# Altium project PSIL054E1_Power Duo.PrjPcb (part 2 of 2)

## Sheet PSIL054E1_FTDI.SchDoc
size 431 x 279 mm; Date: Not shown in title block; ApprovedBy: Not shown in title block; CheckedBy: Not shown in title block; Author: Not shown in title block; CompanyName: Not shown in title block; Engineer: Not shown in title block; Organization: Not shown in title block; Address1: Not shown in title block; Address2: Not shown in title block; Address3: Not shown in title block; Address4: Not shown in title block; DocumentNumber: 1; Revision: Use project parameter SCH_Rev; SheetNumber: 7; SheetTotal: 9; PageSetup: Record=PageOptions¦CenterHorizontal=True¦CenterVertical=True¦PrintScale=1.00¦XCorrection=1.00¦YCorrection=1.00¦PrintKind=0¦BorderSize=5000000¦LeftOffset=0¦BottomOffset=0¦Orientation=2¦PaperLength=1000¦PaperWidth=1000¦Scale=100¦PaperSource=15¦PrintQuality=600¦MediaType=1¦DitherType=10¦PaperKind=Letter¦PrintScaleMode=1
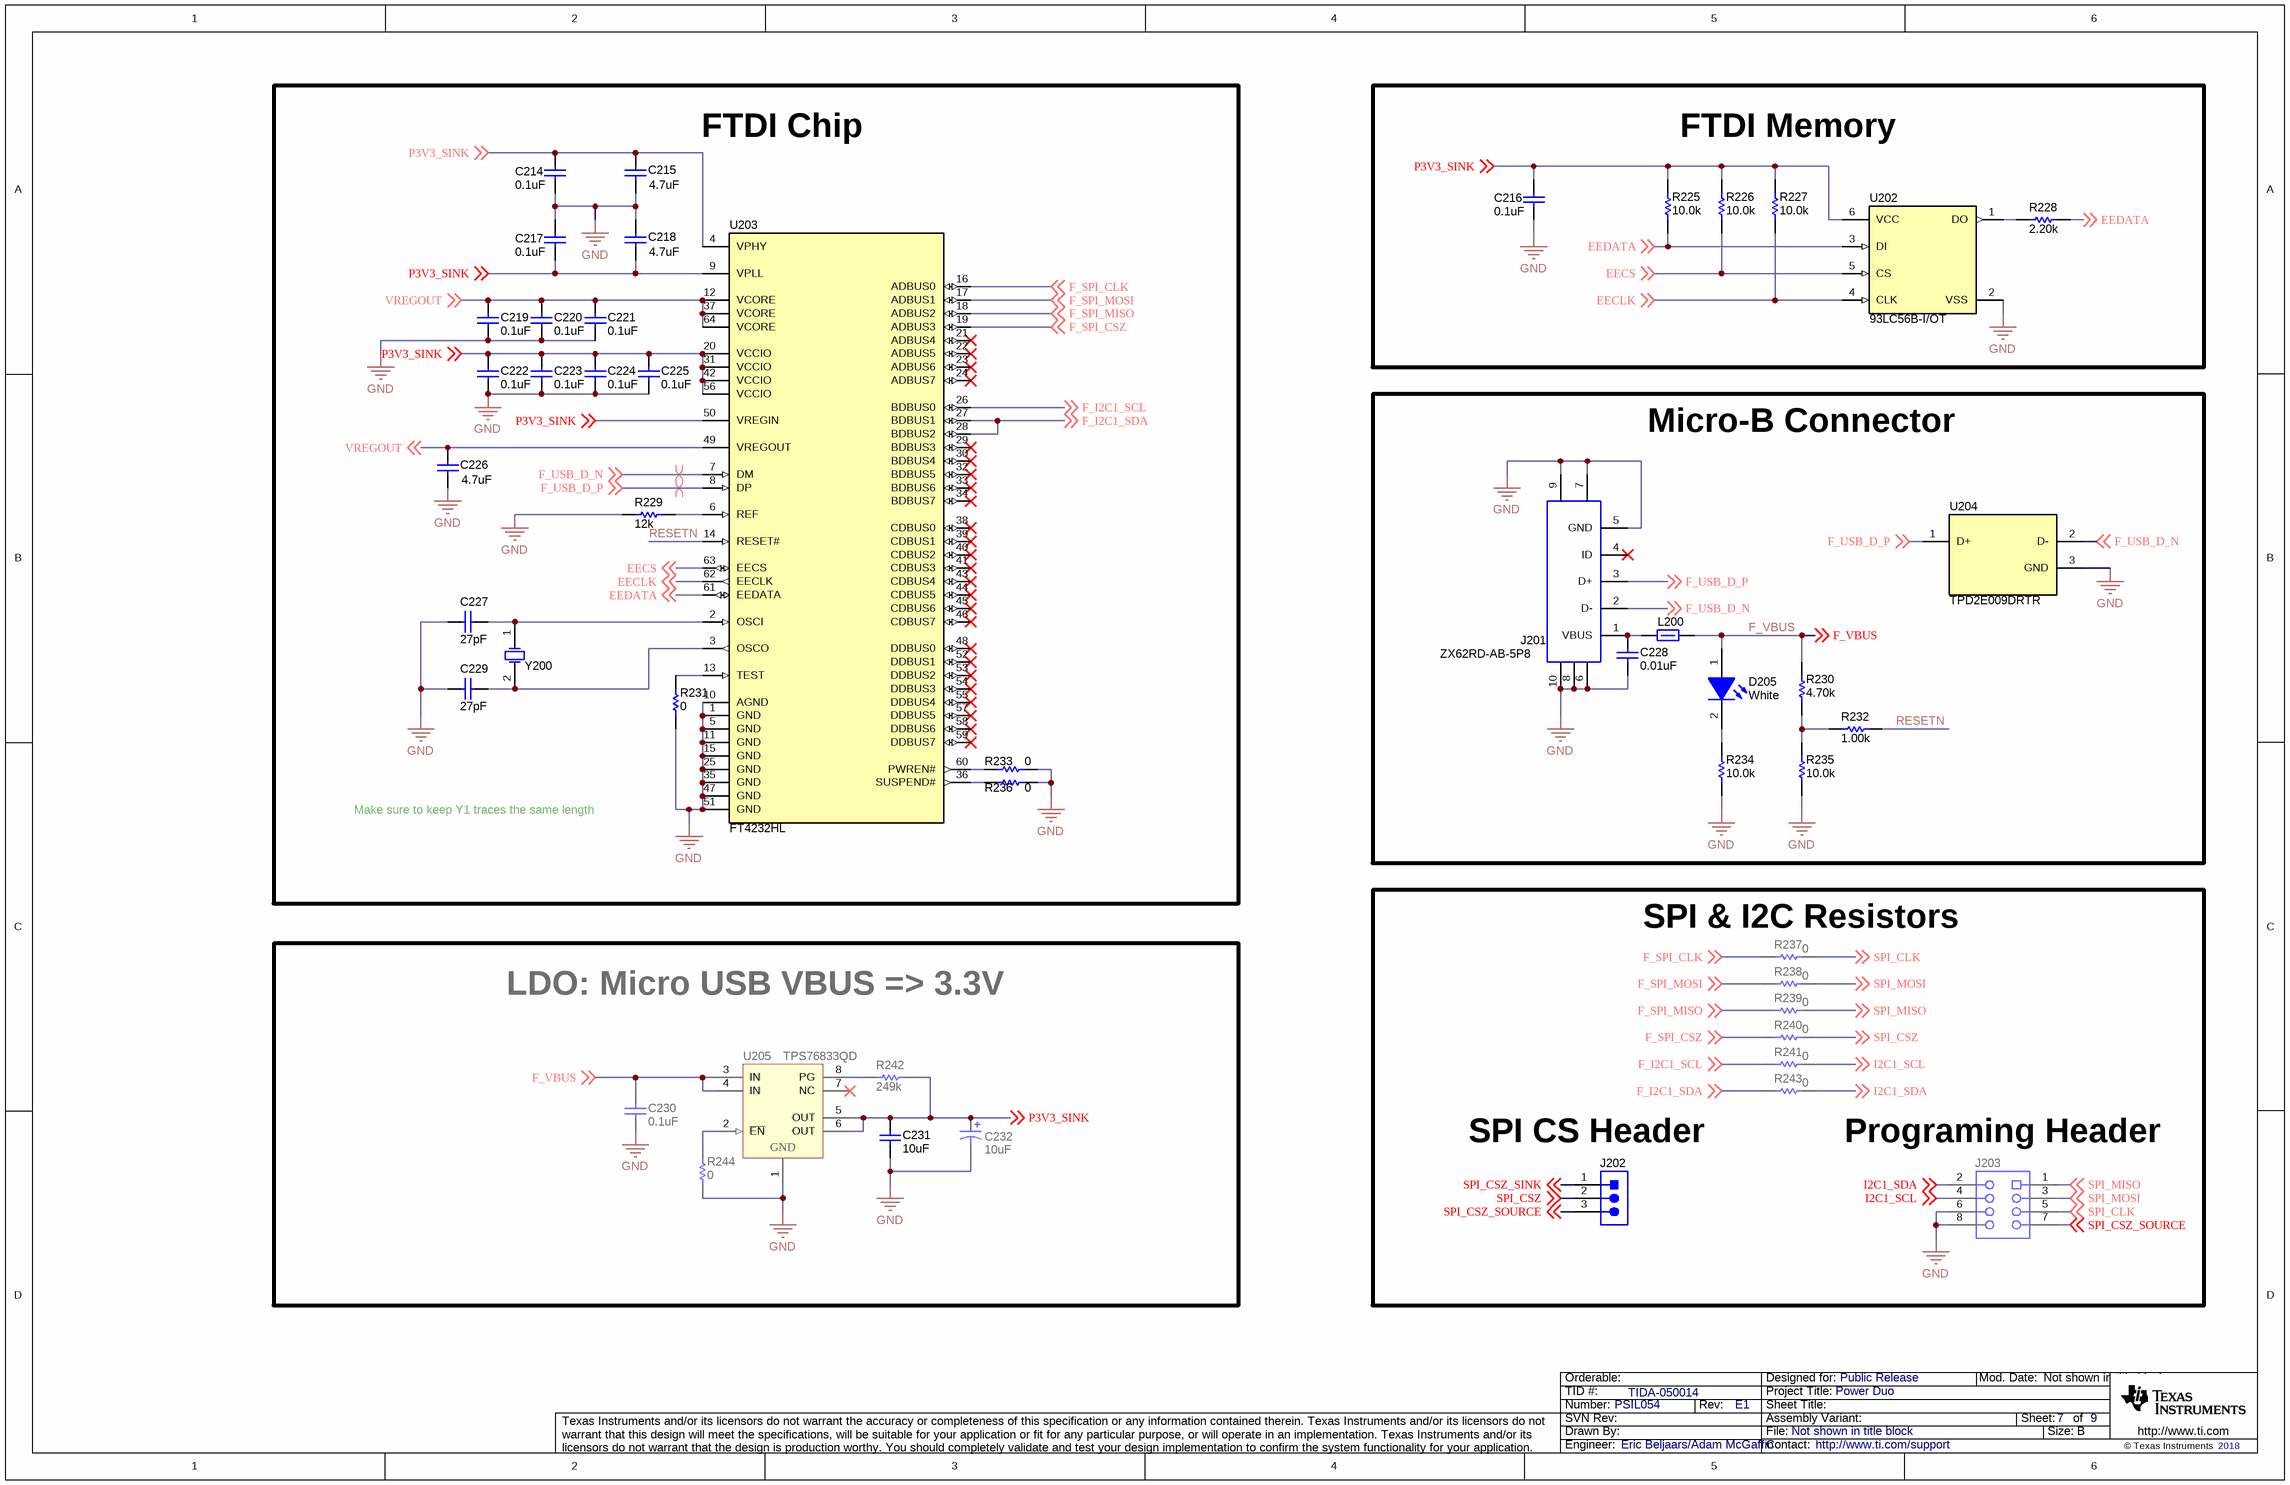
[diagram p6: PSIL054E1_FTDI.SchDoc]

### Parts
C214  value 0.1uF  [0402]  (hidden comment: C1005X7R1H104K050BB)
C215  ValueDisplayed: 4.7uF  [0402]  (hidden comment: C1005X5R1A475M050BC)
C216  value 0.1uF  [0402L]  (hidden comment: C1005X7R1H104K050BB)
C217  value 0.1uF  [0402]  (hidden comment: C1005X7R1H104K050BB)
C218  ValueDisplayed: 4.7uF  [0402]  (hidden comment: C1005X5R1A475M050BC)
C219  value 0.1uF  [0402]  (hidden comment: C1005X7R1H104K050BB)
C220  value 0.1uF  [0402]  (hidden comment: C1005X7R1H104K050BB)
C221  value 0.1uF  [0402]  (hidden comment: C1005X7R1H104K050BB)
C222  value 0.1uF  [0402]  (hidden comment: C1005X7R1H104K050BB)
C223  value 0.1uF  [0402]  (hidden comment: C1005X7R1H104K050BB)
C224  value 0.1uF  [0402]  (hidden comment: C1005X7R1H104K050BB)
C225  value 0.1uF  [0402]  (hidden comment: C1005X7R1H104K050BB)
C226  ValueDisplayed: 4.7uF  [0402]  (hidden comment: C1005X5R1A475M050BC)
C227  ValueDisplayed: 27pF  [0603]  (hidden comment: CL10C270FB8NNNC)
C228  ValueDisplayed: 0.01uF  [0402]  (hidden comment: C0402C103J5RACTU)
C229  ValueDisplayed: 27pF  [0603]  (hidden comment: CL10C270FB8NNNC)
C230  value 0.1uF  [0402]  (hidden comment: C1005X7R1H104K050BB)
C231  ValueDisplayed: 10uF  [0805_HV]  (hidden comment: C2012X5R1V106K085AC)
C232  ValueDisplayed: 10uF  [3528-21]  (hidden comment: 293D106X9010B2TE3)
D205  value White  [LW QH8G_White]  (hidden comment: LW QH8G-Q2S2-3K5L-1)
J201  ZX62RD-AB-5P8  [Hirose_ZX62RD-AB-5P8]
J202  TSW-103-07-G-S  [TSW-103-07-G-S]  (value not drawn)
J203  SSQ-104-03-G-D  [Samtec_SSQ-104-03-x-D]  (value not drawn)
L200  BLM18SG260TN1D  [0603]  (value not drawn)
R225  ValueDisplayed: 10.0k  [0402]  (hidden comment: ERJ-2RKF1002X)
R226  ValueDisplayed: 10.0k  [0402]  (hidden comment: ERJ-2RKF1002X)
R227  ValueDisplayed: 10.0k  [0402]  (hidden comment: ERJ-2RKF1002X)
R228  ValueDisplayed: 2.20k  [0402]  (hidden comment: RC0402FR-072K2L)
R229  value 12k  [0402]  (hidden comment: CRCW040212K0JNED)
R230  ValueDisplayed: 4.70k  [0402]  (hidden comment: ERJ-2RKF4701X)
R231  ValueDisplayed: 0  [0402]  (hidden comment: CRCW04020000Z0ED)
R232  ValueDisplayed: 1.00k  [0402]  (hidden comment: ERJ-2RKF1001X)
R233  ValueDisplayed: 0  [0402]  (hidden comment: CRCW04020000Z0ED)
R234  ValueDisplayed: 10.0k  [0402]  (hidden comment: ERJ-2RKF1002X)
R235  ValueDisplayed: 10.0k  [0402]  (hidden comment: ERJ-2RKF1002X)
R236  ValueDisplayed: 0  [0402]  (hidden comment: CRCW04020000Z0ED)
R237  ValueDisplayed: 0  [0402]  (hidden comment: CRCW04020000Z0ED)
R238  ValueDisplayed: 0  [0402]  (hidden comment: CRCW04020000Z0ED)
R239  ValueDisplayed: 0  [0402]  (hidden comment: CRCW04020000Z0ED)
R240  ValueDisplayed: 0  [0402]  (hidden comment: CRCW04020000Z0ED)
R241  ValueDisplayed: 0  [0402]  (hidden comment: CRCW04020000Z0ED)
R242  ValueDisplayed: 249k  [0603]  (hidden comment: CRCW0603249KFKEA)
R243  ValueDisplayed: 0  [0402]  (hidden comment: CRCW04020000Z0ED)
R244  ValueDisplayed: 0  [0402]  (hidden comment: CRCW04020000Z0ED)
U202  93LC56B-I/OT  [SOT-23-6]
U203  FT4232HL  [LQFP64_N]
U204  TPD2E009DRTR  [DRT0003A]
U205  TPS76833QD  [D0008A_N]
Y200  ECS-120-20-3X-TR  [ECS_CSM-3X]  (value not drawn)

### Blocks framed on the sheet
FTDI Chip: C214 C215 C217-C227 C229 R229 R231 R233 R236 U203 Y200
FTDI Memory: C216 R225-R228 U202
Micro-B Connector: C228 D205 J201 L200 R230 R232 R234 R235 U204
LDO: Micro USB VBUS => 3.3V: C230-C232 R242 R244 U205

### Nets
GND: C214.2 C215.2 C216.2 C217.1 C218.1 C219.2 C220.2 C221.2 C222.2 C223.2 C224.2 C225.2 C226.2 C227.1 C228.2 C229.1 C230.2 C231.2 C232.2(-) J201.5(GND) J201.6 J201.7 J201.8 J201.9 J201.10 J203.6 J203.8 R229.2 R231.2 R233.2 R234.1 R235.1 R236.2 R244.2 U202.2(VSS) U203.1(GND) U203.5(GND) U203.10(AGND) U203.11(GND) U203.15(GND) U203.25(GND) U203.35(GND) U203.47(GND) U203.51(GND) U204.3(GND) U205.1(GND)
EECLK: R227.1 U202.4(CLK) U203.62(EECLK) ; off-sheet EECLK
EECS: R226.1 U202.5(CS) U203.63(EECS) ; off-sheet EECS
EEDATA: R225.1 R228.2 U202.3(DI) U203.61(EEDATA) ; off-sheet EEDATA
F_I2C1_SCL: R241.1 U203.26(BDBUS0) ; off-sheet F_I2C1_SCL
F_I2C1_SDA: R243.1 U203.27(BDBUS1) U203.28(BDBUS2) ; off-sheet F_I2C1_SDA
F_SPI_CLK: R237.1 U203.16(ADBUS0) ; off-sheet F_SPI_CLK
F_SPI_CSZ: R240.1 U203.19(ADBUS3) ; off-sheet F_SPI_CSZ
F_SPI_MISO: R239.1 U203.18(ADBUS2) ; off-sheet F_SPI_MISO
F_SPI_MOSI: R238.1 U203.17(ADBUS1) ; off-sheet F_SPI_MOSI
F_USB_D_N: J201.2(D-) U203.7(DM) U204.2(D-) ; off-sheet F_USB_D_N
F_USB_D_P: J201.3(D+) U203.8(DP) U204.1(D+) ; off-sheet F_USB_D_P
F_VBUS: C230.1 D205.1(A) L200.2 R230.2 U205.3(IN) U205.4(IN) ; off-sheet F_VBUS
I2C1_SCL: J203.4 R241.2 ; off-sheet I2C1_SCL
I2C1_SDA: J203.2 R243.2 ; off-sheet I2C1_SDA
P3V3_SINK: C214.1 C215.1 C216.1 C217.2 C218.2 C222.1 C223.1 C224.1 C225.1 C231.1 C232.1(+) R225.2 R226.2 R227.2 R242.2 U202.6(VCC) U203.4(VPHY) U203.9(VPLL) U203.20(VCCIO) U203.31(VCCIO) U203.42(VCCIO) U203.50(VREGIN) U203.56(VCCIO) U205.5(OUT) U205.6(OUT) ; off-sheet P3V3_SINK
RESETN: R232.2 U203.14(RESET#)
SPI_CLK: J203.5 R237.2 ; off-sheet SPI_CLK
SPI_CSZ: J202.2 R240.2 ; off-sheet SPI_CSZ
SPI_CSZ_SINK: J202.1 ; off-sheet SPI_CSZ_SINK
SPI_CSZ_SOURCE: J202.3 J203.7 ; off-sheet SPI_CSZ_SOURCE
SPI_MISO: J203.1 R239.2 ; off-sheet SPI_MISO
SPI_MOSI: J203.3 R238.2 ; off-sheet SPI_MOSI
VREGOUT: C219.1 C220.1 C221.1 C226.1 U203.12(VCORE) U203.37(VCORE) U203.49(VREGOUT) U203.64(VCORE) ; off-sheet VREGOUT
NetC227_2: C227.2 U203.2(OSCI) Y200.1(OSC1)
NetC228_1: C228.1 J201.1(VBUS) L200.1
NetC229_2: C229.2 U203.3(OSCO) Y200.2(OSC2)
NetD205_2: D205.2(K) R234.2
NetR228_1: R228.1 U202.1(DO)
NetR229_1: R229.1 U203.6(REF)
NetR230_1: R230.1 R232.1 R235.2
NetR231_1: R231.1 U203.13(TEST)
NetR233_1: R233.1 U203.60(PWREN#)
NetR236_1: R236.1 U203.36(SUSPEND#)
NetR242_1: R242.1 U205.8(PG)
NetR244_1: R244.1 U205.2(~{EN})

Not connected (* = marked no-connect by the designer): J201 4(ID)*; U203 21(ADBUS4)* 22(ADBUS5)* 23(ADBUS6)* 24(ADBUS7)* 29(BDBUS3)* 30(BDBUS4)* 32(BDBUS5)* 33(BDBUS6)* 34(BDBUS7)* 38(CDBUS0)* 39(CDBUS1)* 40(CDBUS2)* 41(CDBUS3)* 43(CDBUS4)* 44(CDBUS5)* 45(CDBUS6)* 46(CDBUS7)* 48(DDBUS0)* 52(DDBUS1)* 53(DDBUS2)* 54(DDBUS3)* 55(DDBUS4)* 57(DDBUS5)* 58(DDBUS6)* 59(DDBUS7)*; U205 7(NC)*

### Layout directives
differential pair: F_USB_D_N, F_USB_D_P

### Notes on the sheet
- Make sure to keep Y1 traces the same length
- (near R237) SPI & I2C Resistors
- (near J202) SPI CS Header
- (near J203) Programing Header

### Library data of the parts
C214 C217 C219-C225 C230 = CMP-0006297-1: CAP, CERM, 0.1 uF, 50 V, +/- 10%, X7R, 0402; Manufacturer: TDK; TaMin_C: -55°C; ESR_ohm: 0.039064; Polarized: N; SizeAreaWB_mm2: 3; Value1: 0.039064 ohm; U/M: EA; TaMax_C: 125°C; SizeZ_mm: 0.6; SizeX_mm: 1; SizeY_mm: 0.5; Value2: 50V; CompType: Capacitor; Cap_F: 100nF; IRMS_A: 8.14669dA; AEC Category: Q200
C215 C218 C226 = CMP-0006269-2: CAP, CERM, 4.7 uF, 10 V, +/- 20%, X5R, 0402; Manufacturer: TDK; TaMin_C: -55°C; Polarized: N; SizeAreaWB_mm2: 3; Value1: Unknown; U/M: EA; Value: 4.7uF; TaMax_C: 85°C; SizeZ_mm: 0.6; SizeX_mm: 1; SizeY_mm: 0.5; Value2: 10V; CompType: Capacitor; Cap_F: 4.7µF; AEC Category: Q200
C216 = CMP-0006297-1: CAP, CERM, 0.1 uF, 50 V, +/- 10%, X7R, 0402; Manufacturer: TDK; TaMin_C: -55°C; ESR_ohm: 0.039064; Polarized: N; SizeAreaWB_mm2: 3; Value1: 0.039064 ohm; U/M: EA; TaMax_C: 125°C; SizeZ_mm: 0.6; SizeX_mm: 1; SizeY_mm: 0.5; Cap_Case: 0402; Value2: 50V; CompType: Capacitor; Cap_F: 100nF; IRMS_A: 8.14669dA; AEC Category: Q200
C227 C229 = CMP-0007116-4: CAP, CERM, 27 pF, 50 V, +/- 1%, C0G/NP0, 0603; Manufacturer: Samsung Electro-Mechanics; TaMin_C: -55°C; Polarized: N; SizeAreaWB_mm2: 4.68; Value1: Unknown; U/M: EA; Value: 27pF; TaMax_C: 125°C; SizeZ_mm: 1; SizeX_mm: 1.6; SizeY_mm: 0.8; Value2: 50V; SizeArea_mm2: 1.28; CompType: Capacitor; AEC Category: Q200
C228 = CMP-0006236-2: CAP, CERM, 0.01 uF, 50 V, +/- 5%, X7R, 0402; Manufacturer: Kemet; TaMin_C: -55°C; Polarized: N; SizeAreaWB_mm2: 3; Value1: Unknown; U/M: EA; Value: 0.01uF; TaMax_C: 125°C; SizeZ_mm: 0.6; SizeX_mm: 1; SizeY_mm: 0.5; Value2: 50V; CompType: Capacitor; Cap_F: 10nF; AEC Category: Q200
C231 = CMP-0007842-2: CAP, CERM, 10 uF, 35 V, +/- 10%, X5R, 0805; Manufacturer: TDK; TaMin_C: -55°C; ESR_ohm: 2.818m; Polarized: N; SizeAreaWB_mm2: 6.75; Value1: 0.002818 ohm; U/M: EA; Value: 10uF; TaMax_C: 85°C; SizeZ_mm: 1.45; SizeX_mm: 2; SizeY_mm: 1.25; Cap_Case: 0805; Value2: 35V; SizeArea_mm2: 2.5; CompType: Capacitor; Cap_F: 10µF; IRMS_A: 3.88676A; AEC Category: Q200
C232 = CMP-0011512-2: CAP, TA, 10 uF, 10 V, +/- 10%, 2.5 ohm, SMD; Manufacturer: Vishay-Sprague; TaMin_C: -55°C; ESR_ohm: 2.5; Polarized: Y; SizeAreaWB_mm2: 17.1; Value1: 2.5 ohm; U/M: EA; Value: 10uF; TaMax_C: 125°C; SizeZ_mm: 2.1; SizeX_mm: 3.5; SizeY_mm: 2.8; Cap_Case: B; Value2: 10V; SizeArea_mm2: 9.8; CompType: Capacitor; Cap_F: 10µF; IRMS_A: 1.8dA; AEC Category: Q200
D205 = CMP-0002919-1: LED, White, SMD; Manufacturer: OSRAM; Io_A: 5mA; Vr_V: 5V; Tjmax_C: 95°C; Value1: W; U/M: EA; Angle: 120; Ir_A: 10nA; Vf_V: 2.8V
J201 = CMP-0075126-1: Connector, Receptacle, Micro-USB Type AB, R/A, Bottom Mount SMT; Manufacturer: Hirose Electric Co. Ltd.; Alternate PartNumber: ZX62RD-AB-5P8(30); CNHeader: False; Gender: Female; CompType: USB; Row_Count: 1; Pitch_mm: 0.65; CT: True
J202 = CMP-0075407-2: Header, 100mil, 3x1, Gold, TH; Manufacturer: Samtec; Pitch_mm: 2.54; Cert_VDE: N; Gender: Male; Cert_CSA: Y; Voltage_V: 550V; Green_REACh: Passed; Current_A: 6.3A; Green_Lifecycle: Active; Row_Count: 1
J203 = CMP-0055685-1: Receptacle, 2.54mm, 4x2, Gold, TH; Manufacturer: Samtec; CNHeader: FALSE; Current_A: 6.3A; Gender: Female; Cert_CSA: Y; CompType: Socket Strip; Row_Count: 2; RowSpacing_mm: 2.54; CT: TRUE
L200 = CMP-0003354-2: Ferrite Bead, 26 ohm @ 100 MHz, 6 A, 0603; Manufacturer: MuRata; ZTyp@100MHz_Ohm: 26; SizeAreaWB_mm2: 4.68; DCR_ohm: 7m; Value1: 0.007 ohm; Value: 26 ohm; Imax_A: 6A; SizeZ_mm: 1; SizeX_mm: 1.6; SizeY_mm: 0.8; SizeArea_mm2: 1.28
R225-R227 R234 R235 = CMP-0026658-1: RES, 10.0 k, 1%, 0.1 W, 0402; Manufacturer: Panasonic; Power_W: 100mW; TempCo: 100 ppm/C; Value_Code: 10k0; U/M: EA; Value: 10.0k; EIA_Code: E96; Res_ohm: 10k; SizeX_mm: 1; SizeY_mm: 0.5; SizeZ_mm: 0.6; Value2: 0.1W; VDC_V: 50V; AEC Category: Q200
R228 = CMP-0026729-1: RES, 2.20 k, 1%, 0.063 W, 0402; Manufacturer: Yageo America; Power_W: 63mW; TempCo: 100 ppm/C; Value_Code: 2k20; U/M: EA; Value: 2.20k; Res_ohm: 2.2k; SizeX_mm: 1; SizeY_mm: 0.5; SizeZ_mm: 0.6; Value2: 0.063W; AEC Qualified: N; AEC Category: Q200
R229 = CMP-0026834-2: RES, 12 k, 5%, 0.063 W, 0402; Manufacturer: Vishay-Dale; Power_W: 63mW; TempCo: 200 ppm/C; Value_Code: 12k0; U/M: EA; EIA_Code: E24; SizeX_mm: 1; SizeY_mm: 0.5; SizeZ_mm: 0.6; Value2: 0.063W; CompType: Resistor; VDC_V: 50V; AEC Category: Q200
R230 = CMP-0026700-1: RES, 4.70 k, 1%, 0.1 W, 0402; Manufacturer: Panasonic; Power_W: 100mW; TempCo: 100 ppm/C; Value_Code: 4k70; U/M: EA; Value: 4.70k; Res_ohm: 4.7k; SizeX_mm: 1; SizeY_mm: 0.5; SizeZ_mm: 0.6; Value2: 0.1W; VDC_V: 50V; AEC Category: Q200
R231 R233 R236-R241 R243 R244 = CMP-0026822-3: RES, 0, 5%, 0.063 W, AEC-Q200 Grade 0, 0402; Manufacturer: Vishay-Dale; Power_W: 63mW; TempCo: 200 ppm/C; Value_Code: 0000; Value: 0; EIA_Code: E24; SizeX_mm: 1; SizeY_mm: 0.5; SizeZ_mm: 0.6; Value2: 0.063W; AEC Qualified: Y; VDC_V: 50V; AEC Category: Q200
R232 = CMP-0026657-1: RES, 1.00 k, 1%, 0.1 W, 0402; Manufacturer: Panasonic; Power_W: 100mW; TempCo: 100 ppm/C; Value_Code: 1k00; U/M: EA; Value: 1.00k; EIA_Code: E96; Res_ohm: 1k; SizeX_mm: 1; SizeY_mm: 0.5; SizeZ_mm: 0.6; Value2: 0.1W; VDC_V: 50V; AEC Category: Q200
R242 = CMP-0022234-4: RES, 249 k, 1%, 0.1 W, AEC-Q200 Grade 0, 0603; Manufacturer: Vishay-Dale; Power_W: 100mW; TempCo: 100 ppm/C; Value: 249k; EIA_Code: E96; SizeX_mm: 1.6; SizeY_mm: 0.8; SizeZ_mm: 1; Value2: 0.1W; SizeArea_mm2: 1.28; AEC Qualified: Y; VDC_V: 75V; AEC Category: Q200; AEC Grade: 0
U202 = CMP-0005250-2: 2K Microwire Compatible Serial EEPROM, SOT-23-6; Manufacturer: Microchip; SizeZ_mm: 1.15; SizeX_mm: 2.9; SizeY_mm: 2.8; SizeArea_mm2: 8.12; SizeAreaWB_mm2: 14.82
U203 = CMP-0004747-1: Quad High Speed USB to Multipurpose UART/MPSSE IC; Manufacturer: FTDI
U204 = CMP-0043102-2: ESD Protection Array for High-Speed Data Interfaces, 2 Channels, -40 to +85 degC, 3-pin SOT (DRT), Green (RoHS & no Sb/Br); Manufacturer: Texas Instruments; IO Leakage Current(nA): 10; IO Capacitance(Typ)(pF): 0.7; Serial ATA / eSATA: TRUE; SubFamily: ESD Solution; Breakdown Voltage(Min)(V): 9; Differential Capacitance(pF): 0.01; IEC 61000-4-2 Air-Gap(+/- kV): 8
U205 = CMP-0036484-1: Single Output Fast Transient Response LDO, 1 A, Fixed 3.3 V Output, 2.7 to 10 V Input, with Low IQ, 8-pin SOIC (D), -40 to 125 degC, Green (RoHS & no Sb/Br); Manufacturer: Texas Instruments; Iout(Max)(A): 1; SubFamily: Single Channel LDO; Accuracy(%): 2; Vout Adj(Max)(V): 3.3; Power Good: TRUE; Vin(Min)(V): 2.7; Vdo(Typ)(mV): 350; Iq(Typ)(mA): 0.08; Vin(Max)(V): 10
Y200 = CMP-0004584-3: CRYSTAL, 12 MHz, 20pF, SMD; Manufacturer: ECS Inc.; TaMin_C: -10°C; Frequency Stability: +/-50ppm; Frequency_Fixed: 12MHz; TaMax_C: 70°C

## Sheet PSIL054E1_Sink Buttons LEDs.SchDoc
size 431 x 279 mm; Date: Not shown in title block; ApprovedBy: Not shown in title block; CheckedBy: Not shown in title block; Author: Not shown in title block; CompanyName: Not shown in title block; Engineer: Not shown in title block; Organization: Not shown in title block; Address1: Not shown in title block; Address2: Not shown in title block; Address3: Not shown in title block; Address4: Not shown in title block; DocumentNumber: 1; Revision: Use project parameter SCH_Rev; SheetNumber: 8; SheetTotal: 9; PageSetup: Record=PageOptions¦CenterHorizontal=True¦CenterVertical=True¦PrintScale=1.00¦XCorrection=1.00¦YCorrection=1.00¦PrintKind=0¦BorderSize=5000000¦LeftOffset=0¦BottomOffset=0¦Orientation=2¦PaperLength=1000¦PaperWidth=1000¦Scale=100¦PaperSource=15¦PrintQuality=600¦MediaType=1¦DitherType=10¦PaperKind=Letter¦PrintScaleMode=1
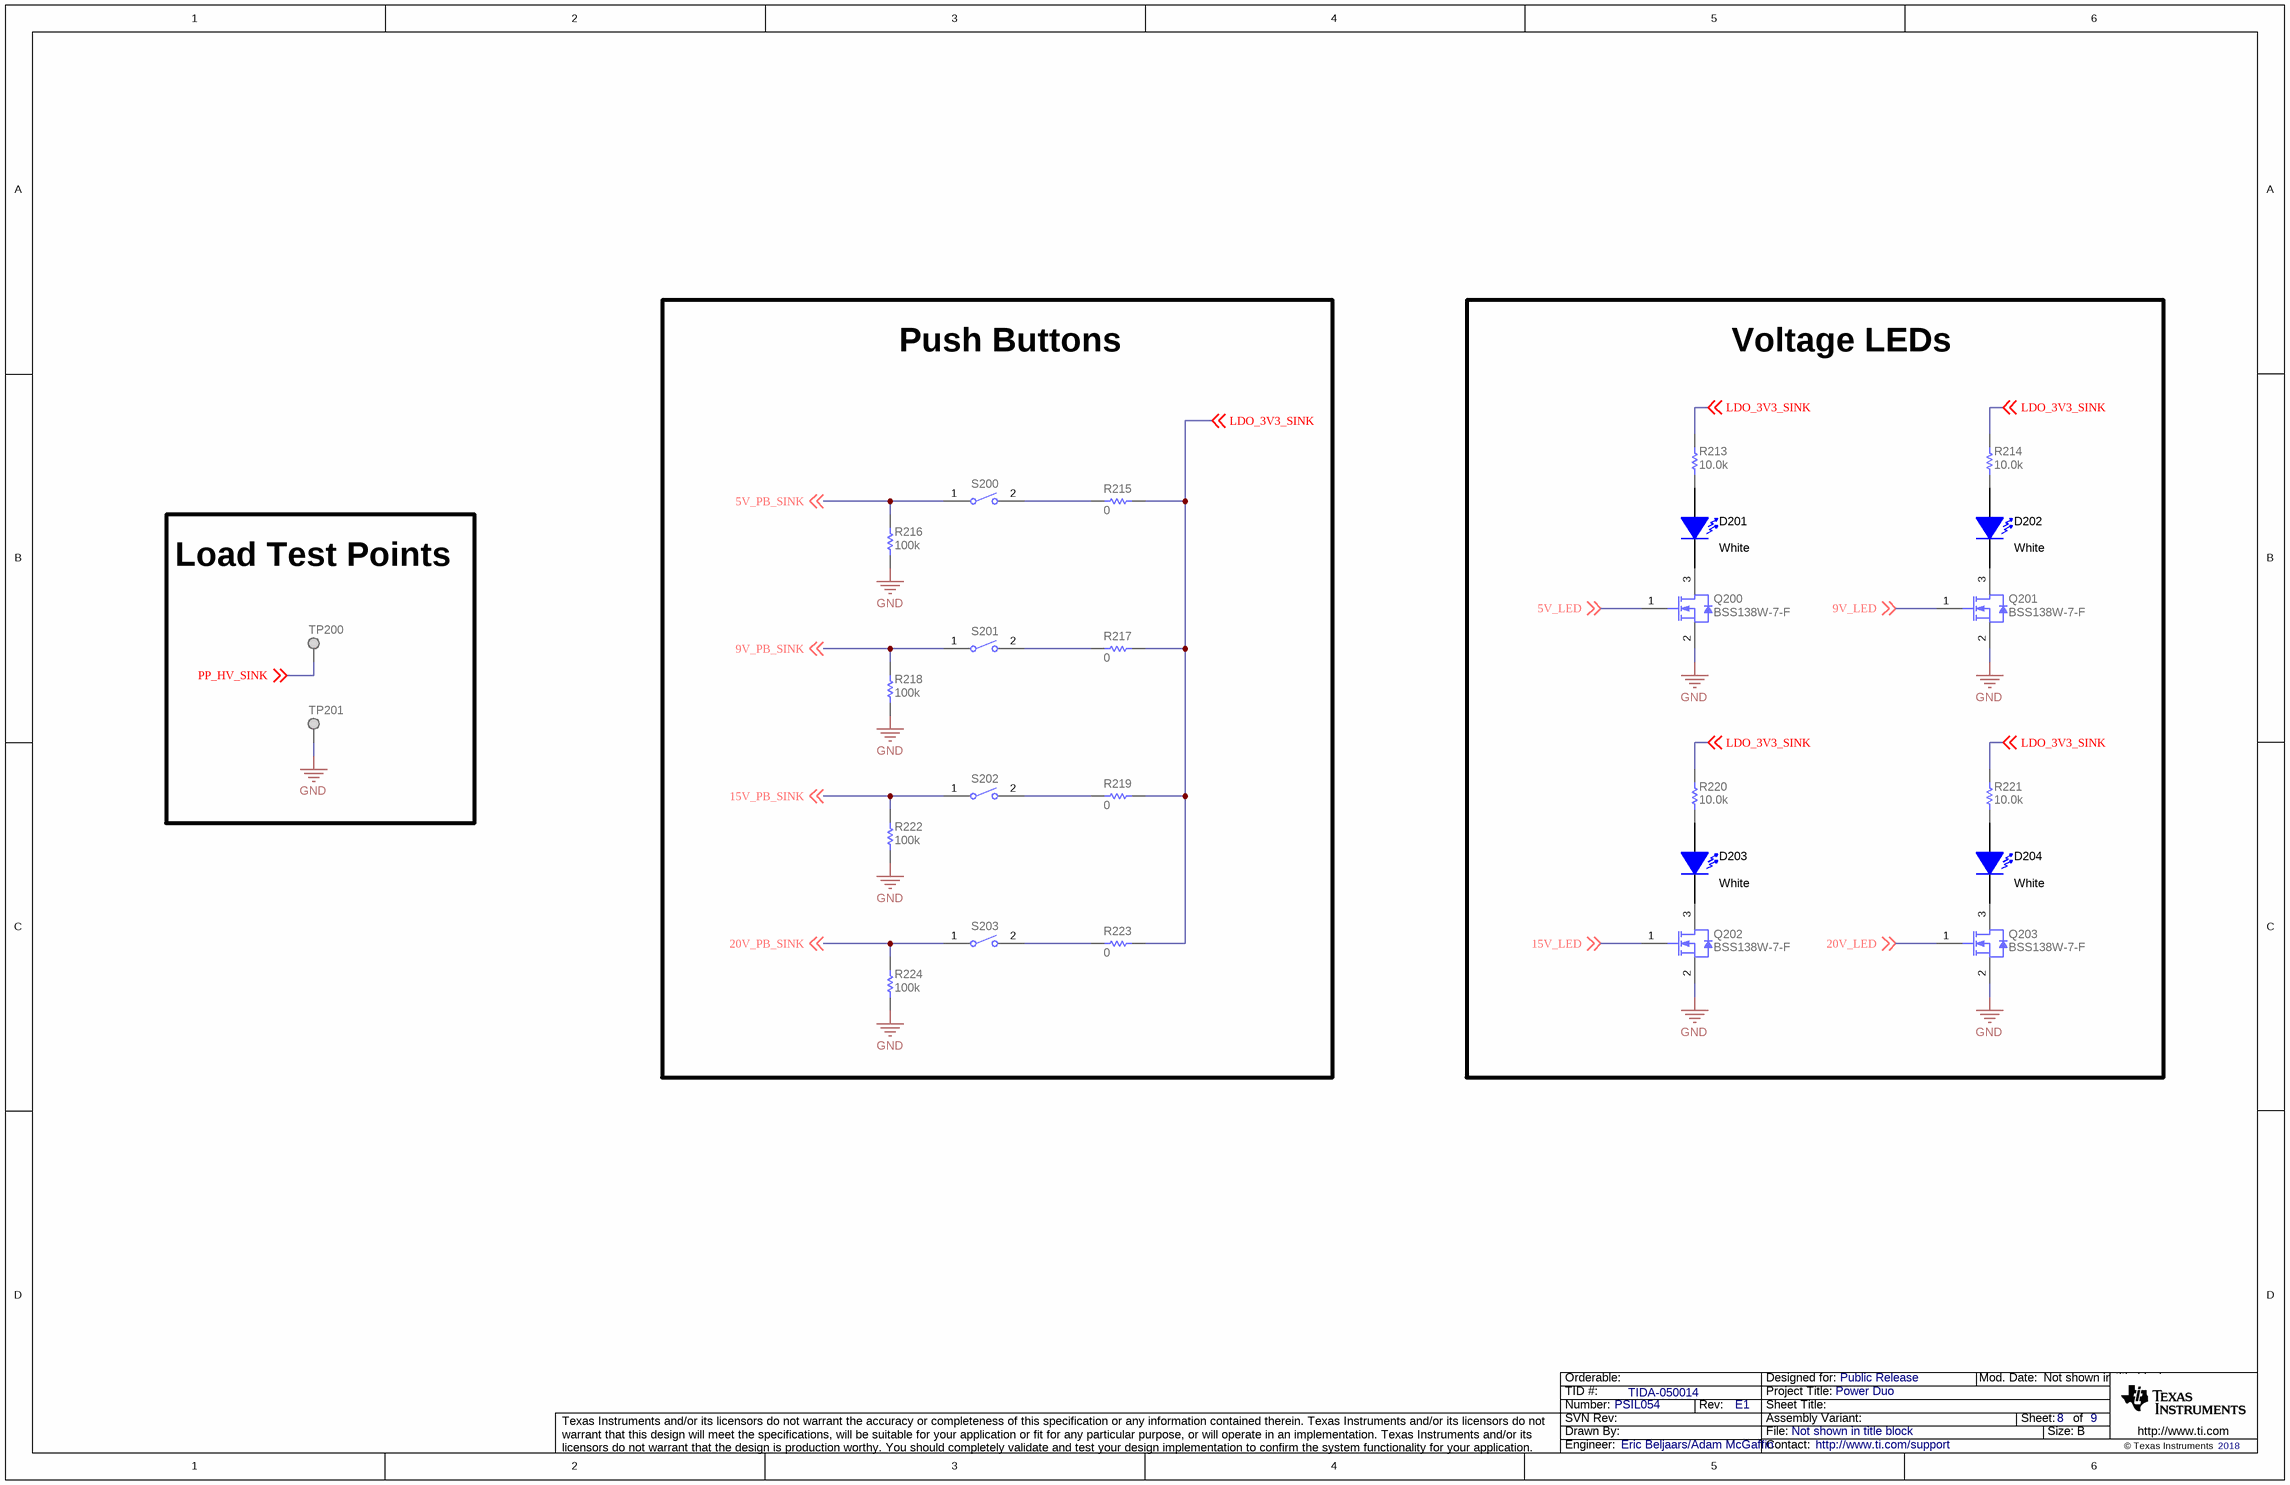
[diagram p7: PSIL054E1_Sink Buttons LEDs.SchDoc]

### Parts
D201  value White  [LW QH8G_White]  (hidden comment: LW QH8G-Q2S2-3K5L-1)
D202  value White  [LW QH8G_White]  (hidden comment: LW QH8G-Q2S2-3K5L-1)
D203  value White  [LW QH8G_White]  (hidden comment: LW QH8G-Q2S2-3K5L-1)
D204  value White  [LW QH8G_White]  (hidden comment: LW QH8G-Q2S2-3K5L-1)
Q200  BSS138W-7-F  [SOT-323]
Q201  BSS138W-7-F  [SOT-323]
Q202  BSS138W-7-F  [SOT-323]
Q203  BSS138W-7-F  [SOT-323]
R213  ValueDisplayed: 10.0k  [TNPW0603]  (hidden comment: TNPW060310K0BEEA)
R214  ValueDisplayed: 10.0k  [TNPW0603]  (hidden comment: TNPW060310K0BEEA)
R215  ValueDisplayed: 0  [0402]  (hidden comment: CRCW04020000Z0EDHP)
R216  ValueDisplayed: 100k  [0402]  (hidden comment: CRCW0402100KDHEDP)
R217  ValueDisplayed: 0  [0402]  (hidden comment: CRCW04020000Z0EDHP)
R218  ValueDisplayed: 100k  [0402]  (hidden comment: CRCW0402100KDHEDP)
R219  ValueDisplayed: 0  [0402]  (hidden comment: CRCW04020000Z0EDHP)
R220  ValueDisplayed: 10.0k  [TNPW0603]  (hidden comment: TNPW060310K0BEEA)
R221  ValueDisplayed: 10.0k  [TNPW0603]  (hidden comment: TNPW060310K0BEEA)
R222  ValueDisplayed: 100k  [0402]  (hidden comment: CRCW0402100KDHEDP)
R223  ValueDisplayed: 0  [0402]  (hidden comment: CRCW04020000Z0EDHP)
R224  ValueDisplayed: 100k  [0402]  (hidden comment: CRCW0402100KDHEDP)
S200  434121025816  [SW_434121025816]  (value not drawn)
S201  434121025816  [SW_434121025816]  (value not drawn)
S202  434121025816  [SW_434121025816]  (value not drawn)
S203  434121025816  [SW_434121025816]  (value not drawn)
TP200  5019  [Keystone_5019]  (value not drawn)
TP201  5019  [Keystone_5019]  (value not drawn)

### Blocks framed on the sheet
Push Buttons: R215-R219 R222-R224 S200-S203
Voltage LEDs: D201-D204 Q200-Q203 R213 R214 R220 R221
Load Test Points: TP200 TP201

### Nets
GND: Q200.2(S) Q201.2(S) Q202.2(S) Q203.2(S) R216.1 R218.1 R222.1 R224.1 TP201.1
5V_LED: Q200.1(G) ; off-sheet 5V_LED
5V_PB_SINK: R216.2 S200.1 ; off-sheet 5V_PB_SINK
9V_LED: Q201.1(G) ; off-sheet 9V_LED
9V_PB_SINK: R218.2 S201.1 ; off-sheet 9V_PB_SINK
15V_LED: Q202.1(G) ; off-sheet 15V_LED
15V_PB_SINK: R222.2 S202.1 ; off-sheet 15V_PB_SINK
20V_LED: Q203.1(G) ; off-sheet 20V_LED
20V_PB_SINK: R224.2 S203.1 ; off-sheet 20V_PB_SINK
LDO_3V3_SINK: R213.2 R214.2 R215.2 R217.2 R219.2 R220.2 R221.2 R223.2 ; off-sheet LDO_3V3_SINK
PP_HV_SINK: TP200.1 ; off-sheet PP_HV_SINK
NetD201_1: D201.1(A) R213.1
NetD201_2: D201.2(K) Q200.3(D)
NetD202_1: D202.1(A) R214.1
NetD202_2: D202.2(K) Q201.3(D)
NetD203_1: D203.1(A) R220.1
NetD203_2: D203.2(K) Q202.3(D)
NetD204_1: D204.1(A) R221.1
NetD204_2: D204.2(K) Q203.3(D)
NetR215_1: R215.1 S200.2
NetR217_1: R217.1 S201.2
NetR219_1: R219.1 S202.2
NetR223_1: R223.1 S203.2

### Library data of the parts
D201-D204 = LW QH8G-Q2S2-3K5L-1: LED, White, SMD; Manufacturer: OSRAM; Vf_V: 2.8; Value2: 2.8V; Io_A: 0.005; Vr_V: 5; Ir_A: 1e-008; Tjmax_C: 95; Value1: W; Angle: 120; U/M: EA
Q200-Q203 = CMP-0000757-1: MOSFET, N-CH, 50 V, 0.2 A, SOT-323; Alternate Manufacturer: None; Manufacturer: Diodes Inc.; SizeZ_mm: 1.1; ChType: N; Value1: 3; VdsMax_V: 50V; SizeX_mm: 2.2; Vgs_V: 1.5V; Value: 50V; Rdson45_ohm: 3.5; SizeArea_mm2: 4.84; AEC Category: Q101; IdsMax_A: 2dA; SizeAreaWB_mm2: 10.24; U/M: EA
R213 R214 R220 R221 = CMP-0025686-1: RES, 10.0 k, 0.1%, 0.1 W, AEC-Q200 Grade 1, 0603; Manufacturer: Vishay-Dale; Power_W: 100mW; TempCo: 25 ppm/C; Value_Code: 10k0; U/M: EA; Value: 10.0k; EIA_Code: E192; Res_ohm: 10k; SizeX_mm: 1.6; SizeY_mm: 0.85; SizeZ_mm: 0.55; Value2: 0.1W; SizeArea_mm2: 1.36; AEC Qualified: Y; VDC_V: 75V; AEC Grade: 1; AEC Category: Q200
R215 R217 R219 R223 = CMP-0081856-1: RES, 0, 0%, 0.2 W, AEC-Q200 Grade 0, 0402; Manufacturer: Vishay-Dale; SizeAreaWB_mm2: 3; SizeArea_mm2: 0.5; AEC Qualified: Y; AEC Category: Q200; Value: 0; SizeZ_mm: 0.6; Power_W: 200mW; VDC_V: 50V; Value2: 0.2W; SizeX_mm: 1
R216 R218 R222 R224 = CMP-0026768-2: RES, 100 k, 0.5%, 0.063 W, AEC-Q200 Grade 0, 0402; Manufacturer: Vishay-Dale; Power_W: 63mW; TempCo: 50 ppm/C; Value: 100k; EIA_Code: E192; SizeX_mm: 1; SizeY_mm: 0.5; SizeZ_mm: 0.6; Value2: 0.063W; AEC Qualified: Y; VDC_V: 50V; AEC Category: Q200; AEC Grade: 0
S200-S203 = CMP-0002196-2: Switch, Tactile, SPST, 12 V, SMD; Manufacturer: Wurth Elektronik; CurrentRating_mA: 50A; PositionCount: 1; VDC_V: 12V; SwitchFunction: Off-On
TP200 TP201 = CMP-0055162-1: Test Point, Miniature, SMT; Manufacturer: Keystone; CNHeader: FALSE; Green_Lifecycle: Active; Green_REACh: Passed; CT: TRUE

## Sheet PSIL054E1_EVM_Hardware.SchDoc
size 431 x 279 mm; Date: Not shown in title block; ApprovedBy: Not shown in title block; CheckedBy: Not shown in title block; Author: Not shown in title block; CompanyName: Not shown in title block; Engineer: Not shown in title block; Organization: Not shown in title block; Address1: Not shown in title block; Address2: Not shown in title block; Address3: Not shown in title block; Address4: Not shown in title block; DocumentNumber: 1; Revision: Use project parameter SCH_Rev; SheetNumber: 9; SheetTotal: 9; PageSetup: Record=PageOptions¦CenterHorizontal=True¦CenterVertical=True¦PrintScale=1.00¦XCorrection=1.00¦YCorrection=1.00¦PrintKind=0¦BorderSize=5000000¦LeftOffset=0¦BottomOffset=0¦Orientation=2¦PaperLength=1000¦PaperWidth=1000¦Scale=100¦PaperSource=15¦PrintQuality=600¦MediaType=1¦DitherType=10¦PaperKind=Letter¦PrintScaleMode=1
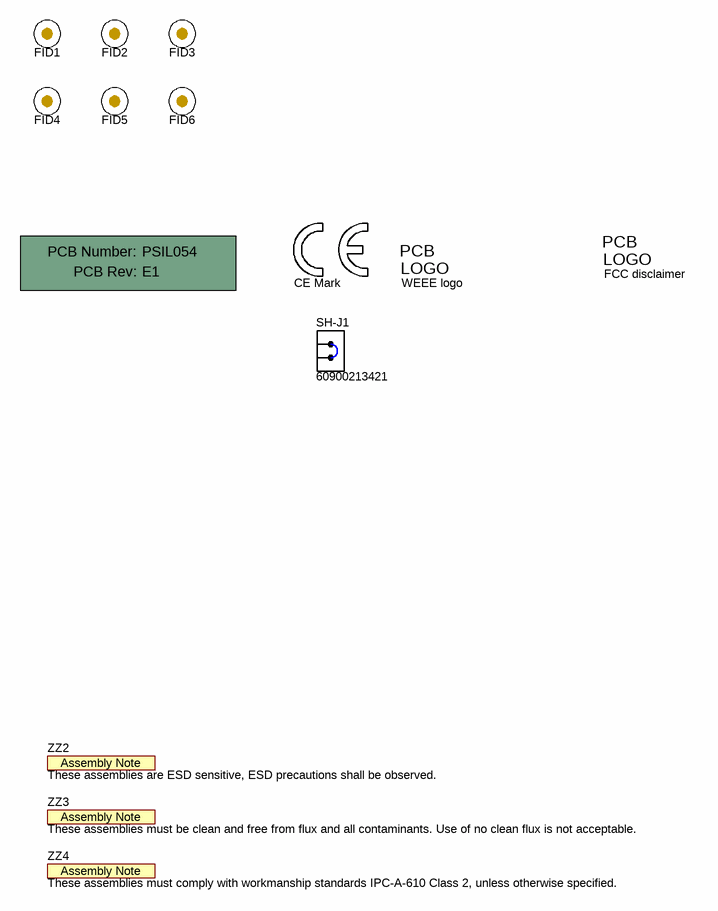
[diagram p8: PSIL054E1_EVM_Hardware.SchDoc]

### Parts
!PCB1  Printed Circuit Board  (value not drawn)  (mechanical)
FID1  Fiducial  [Fiducial10-20]  (value not drawn)
FID2  Fiducial  [Fiducial10-20]  (value not drawn)
FID3  Fiducial  [Fiducial10-20]  (value not drawn)
FID4  Fiducial  [Fiducial10-20]  (value not drawn)
FID5  Fiducial  [Fiducial10-20]  (value not drawn)
FID6  Fiducial  [Fiducial10-20]  (value not drawn)
Logo200  CE Mark  [CE_Mark_5mm]  (no BOM)
Logo203  WEEE logo  [WEEE_Minimum]  (no BOM)
Logo?  FCC disclaimer  [FCC_disclaimer]  (no BOM)
SH-J1  60900213421  [Wurth_60900213421]
ZZ2  These assemblies are ESD sensitive, ESD precautions shall be observed.  [AssemblyNote]  (no BOM)
ZZ3  These assemblies must be clean and free from flux and all contaminants. Use of no clean flux is not acceptable.  [AssemblyNote]  (no BOM)
ZZ4  These assemblies must comply with workmanship standards IPC-A-610 Class 2, unless otherwise specified.  [AssemblyNote]  (no BOM)

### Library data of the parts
!PCB1 = PCB: Manufacturer: Any; PartNumber: PSIL054; SymbolCreator: a0412235
FID1-FID3 = Fiducial: Fiducial mark.  There is nothing to buy or mount.; SymbolCreator: codlsc
FID4-FID6 = CMP-0077181-1: Fiducial mark.  There is nothing to buy or mount.
Logo200 = CMP-0074844-1: SymbolCreator: a0412235
Logo203 = CMP-0074769-1
Logo? = CMP-0074847-1: FCC_disclaimer
SH-J1 = CMP-0003761-2: Shunt, 2.54mm, Gold, Black; Manufacturer: Wurth Elektronik
ZZ2 = CMP-0077236-1
ZZ3 = CMP-0077237-1
ZZ4 = CMP-0077238-1

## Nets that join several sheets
GND: PSIL054E1_Variable DCDC (48 pins), PSIL054E1_Source PD Controller (26 pins), PSIL054E1_Bypass Power Path (C12.2 C13.2 Q11.2 R32.1), PSIL054E1_Source Type-C Connector (15 pins), PSIL054E1_Sink PD Controller (34 pins), PSIL054E1_FTDI (46 pins), PSIL054E1_Sink Buttons LEDs (9 pins)
5V_LED: PSIL054E1_Sink PD Controller (U200.16), PSIL054E1_Sink Buttons LEDs (Q200.1)
5V_PB_SINK: PSIL054E1_Sink PD Controller (U200.44), PSIL054E1_Sink Buttons LEDs (R216.2 S200.1)
9V_LED: PSIL054E1_Sink PD Controller (U200.17), PSIL054E1_Sink Buttons LEDs (Q201.1)
9V_PB_SINK: PSIL054E1_Sink PD Controller (U200.41), PSIL054E1_Sink Buttons LEDs (R218.2 S201.1)
15V_LED: PSIL054E1_Sink PD Controller (U200.18), PSIL054E1_Sink Buttons LEDs (Q202.1)
15V_PB_SINK: PSIL054E1_Sink PD Controller (U200.42), PSIL054E1_Sink Buttons LEDs (R222.2 S202.1)
20V_LED: PSIL054E1_Sink PD Controller (U200.21), PSIL054E1_Sink Buttons LEDs (Q203.1)
20V_PB_SINK: PSIL054E1_Sink PD Controller (U200.43), PSIL054E1_Sink Buttons LEDs (R224.2 S203.1)
C_USB_N: PSIL054E1_Source PD Controller (U5.53), PSIL054E1_Source Type-C Connector (J3.A7 J3.B7)
C_USB_P: PSIL054E1_Source PD Controller (U5.50), PSIL054E1_Source Type-C Connector (J3.A6 J3.B6)
CC1: PSIL054E1_Source PD Controller (C18.1 U5.24), PSIL054E1_Source Type-C Connector (J3.A5)
CC2: PSIL054E1_Source PD Controller (C19.1 U5.26), PSIL054E1_Source Type-C Connector (J3.B5)
I2C1_SCL: PSIL054E1_Source PD Controller (R36.1 R48.2 R50.1 U5.27), PSIL054E1_Sink PD Controller (R201.1 U200.27), PSIL054E1_FTDI (J203.4 R241.2)
I2C1_SDA: PSIL054E1_Source PD Controller (R37.1 R49.2 R51.1 U5.28), PSIL054E1_Sink PD Controller (R202.1 U200.28), PSIL054E1_FTDI (J203.2 R243.2)
LDO_3V3_SINK: PSIL054E1_Sink PD Controller (15 pins), PSIL054E1_Sink Buttons LEDs (8 pins)
P3V3: PSIL054E1_Variable DCDC (10 pins), PSIL054E1_Source PD Controller (6 pins)
PDO_0: PSIL054E1_Variable DCDC (Q6.1), PSIL054E1_Source PD Controller (U5.42)
PDO_1: PSIL054E1_Variable DCDC (Q2.1 Q7.1 R11.2), PSIL054E1_Source PD Controller (U5.43)
PDO_2: PSIL054E1_Variable DCDC (Q3.1 Q8.1 R12.2), PSIL054E1_Source PD Controller (U5.49)
PDO_3: PSIL054E1_Variable DCDC (Q4.1 Q9.1 R13.2), PSIL054E1_Source PD Controller (U5.54)
PP_EXT_EN: PSIL054E1_Source PD Controller (U5.16), PSIL054E1_Bypass Power Path (R31.2)
PP_HV: PSIL054E1_Variable DCDC (7 pins), PSIL054E1_Source PD Controller (6 pins), PSIL054E1_Bypass Power Path (R23.2)
PP_HV_SINK: PSIL054E1_Sink PD Controller (6 pins), PSIL054E1_Sink Buttons LEDs (TP200.1)
SPI_CLK: PSIL054E1_Source PD Controller (R54.1 U5.38 U6.6), PSIL054E1_Sink PD Controller (U200.38 U201.6), PSIL054E1_FTDI (J203.5 R237.2)
SPI_CSZ: PSIL054E1_Sink PD Controller (R205.1), PSIL054E1_FTDI (J202.2 R240.2)
SPI_CSZ_SINK: PSIL054E1_Sink PD Controller (U200.39 U201.1), PSIL054E1_FTDI (J202.1)
SPI_CSZ_SOURCE: PSIL054E1_Source PD Controller (R39.2 R56.1 U5.39 U6.1), PSIL054E1_FTDI (J202.3 J203.7)
SPI_MISO: PSIL054E1_Source PD Controller (5 pins), PSIL054E1_Sink PD Controller (R206.1 U200.36 U201.2), PSIL054E1_FTDI (J203.1 R239.2)
SPI_MOSI: PSIL054E1_Source PD Controller (R55.2 U5.37 U6.5), PSIL054E1_Sink PD Controller (U200.37 U201.5), PSIL054E1_FTDI (J203.3 R238.2)
SYS_PWR: PSIL054E1_Variable DCDC (23 pins), PSIL054E1_Bypass Power Path (R22.1)

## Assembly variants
001: not fitted C16 FID1 FID2 FID3 FID4 FID5 FID6 R26 R43 R48 R49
